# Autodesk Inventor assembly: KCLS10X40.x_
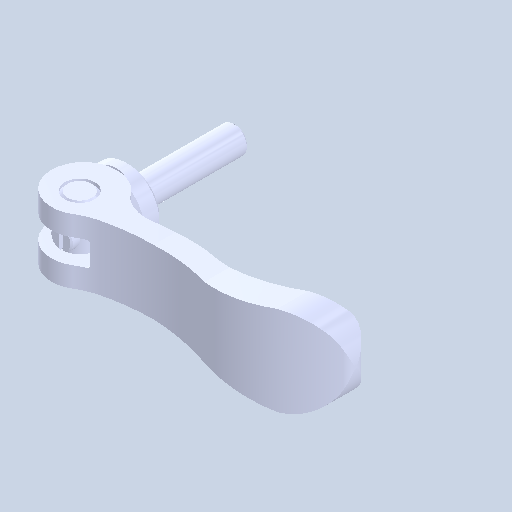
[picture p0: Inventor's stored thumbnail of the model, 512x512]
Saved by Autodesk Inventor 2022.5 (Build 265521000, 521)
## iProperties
Created: 2024-08
Part Number: KCLS10X40.x_
Document SubType Name: Assembly
Designer: ImaoCorp
Author: ImaoCorp
Sending System: SOLIDWORKS 2022-2022290
MC: AMD64
MC_MODEL: Intel64 Family 6 Model 60 Stepping 3, GenuineIntel
OS: Windows_NT
FRU: Parasolid Version 33.1, build 260,  4-25-2022
FORMAT: text
GUISE: transmit
KEY: FILEKCLS10X40.x_t
DATE: Thu Aug 29 10:55:21 2024
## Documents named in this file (5)
- Y:\5.更新分\2024年対応\1001_KCL\データ\kcls10x40\KCLS10X40.x_.iam
- Y:\5.更新分\2024年対応\1001_KCL\データ\kcls10x40\KCLS10X40_01.ipt
- Y:\5.更新分\2024年対応\1001_KCL\データ\kcls10x40\KCLS10X40_02.ipt
- Y:\5.更新分\2024年対応\1001_KCL\データ\kcls10x40\KCLS10X40_03.ipt
- Y:\5.更新分\2024年対応\1001_KCL\データ\kcls10x40\KCLS10X40_04.ipt
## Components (4 placed, 4 different names)
1. KCLS10X40_01
2. KCLS10X40_02
3. KCLS10X40_03
4. KCLS10X40_04
